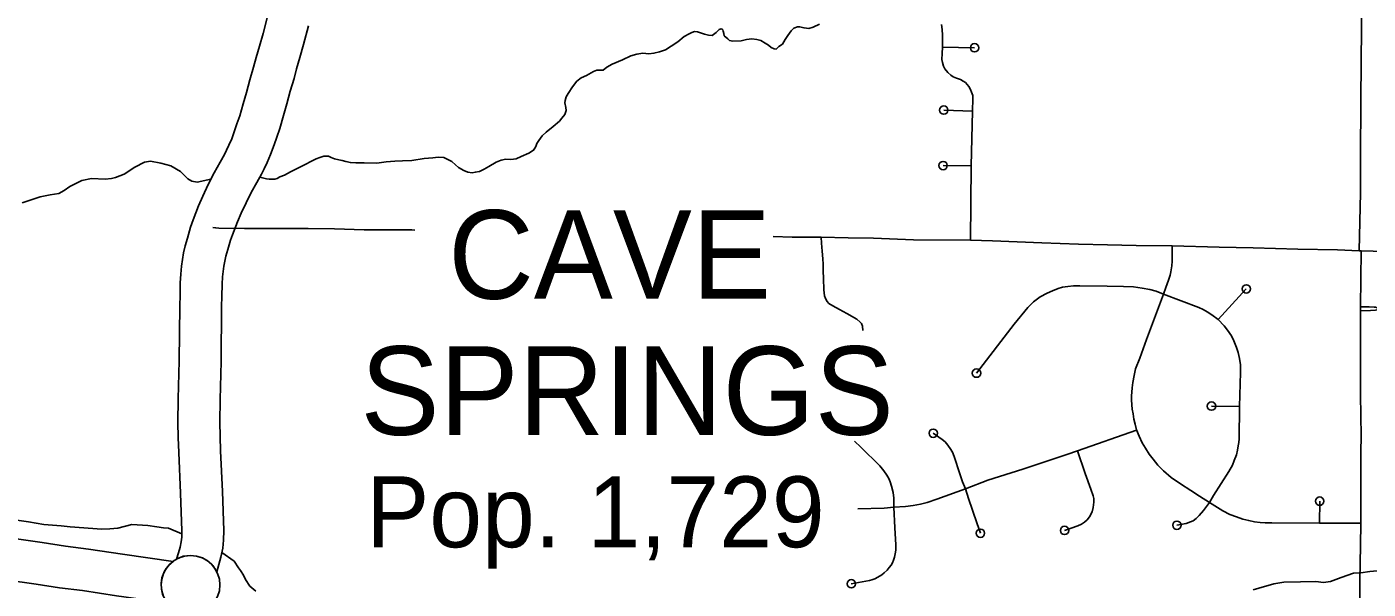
# Model space of a CAD drawing. Extents: x 670147 to 673275, y 705573 to 707613.
# Drawn here: x 671245.2 to 671405.1, y 706403.8 to 706470.8 of the extents above; entities that cross this region are included whole.
import ezdxf

# ---------------------------------------------------------------- set-up
doc = ezdxf.new("R2010")
doc.units = 0
for name, color, linetype in [('10', 7, 'Continuous'), ('24', 7, 'Continuous'), ('33', 7, 'Continuous'), ('34', 7, 'Continuous'), ('35', 7, 'Continuous'), ('6', 7, 'Continuous')]:
    doc.layers.add(name, color=color, linetype=linetype)

msp = doc.modelspace()

# ---------------------------------------------------------------- linework, layer by layer
at = {"layer": '10'}
for points in [[(671273.98, 706472.2), (671273.39, 706470.02), (671272.98, 706468.53), (671272.57, 706467.15), (671272.27, 706466), (671271.83, 706464.52), (671271.41, 706462.99), (671271.02, 706461.63), (671270.61, 706460.21), (671270.29, 706459.25), (671270.01, 706458.41), (671269.67, 706457.48), (671269.33, 706456.72), (671269.05, 706456.13), (671268.79, 706455.6), (671268.28, 706454.69), (671267.56, 706453.42), (671266.87, 706452.03), (671266.21, 706450.64), (671265.72, 706449.48), (671265.07, 706447.8), (671264.75, 706446.95), (671264.38, 706445.62), (671264.13, 706444.74), (671263.93, 706443.9), (671263.8, 706443.09), (671263.67, 706442.31), (671263.58, 706441.34), (671263.53, 706440.33), (671263.51, 706438.83), (671263.46, 706437.59), (671263.4, 706431), (671263.29, 706426.5), (671263.26, 706423.68), (671263.29, 706421.87), (671263.34, 706420.11), (671263.57, 706415.25), (671263.72, 706410.75), (671263.71, 706409.99), (671263.65, 706409.46), (671263.52, 706408.8), (671263.33, 706408.13), (671263.1, 706407.39), (671263.88, 706407.72), (671264.74, 706407.82), (671265.47, 706407.74), (671266.18, 706407.54), (671266.89, 706407.09), (671267.41, 706406.61), (671267.89, 706405.88)], [(671267.89, 706405.88), (671268.38, 706407.63), (671268.59, 706408.69), (671268.7, 706409.66), (671268.72, 706410.79), (671268.57, 706415.45), (671268.33, 706420.29), (671268.29, 706421.98), (671268.26, 706423.7), (671268.29, 706426.41), (671268.4, 706430.92), (671268.46, 706437.48), (671268.5, 706438.7), (671268.53, 706440.17), (671268.57, 706441.01), (671268.63, 706441.68), (671268.73, 706442.28), (671268.83, 706442.91), (671268.97, 706443.48), (671269.19, 706444.28), (671269.51, 706445.4), (671269.74, 706446.02), (671270.35, 706447.59), (671270.78, 706448.6), (671271.37, 706449.86), (671271.97, 706451.07), (671272.64, 706452.25), (671273.2, 706453.25), (671273.53, 706453.91), (671273.89, 706454.64), (671274.3, 706455.61), (671274.73, 706456.76), (671275.04, 706457.69), (671275.38, 706458.72), (671275.83, 706460.25), (671276.22, 706461.65), (671276.64, 706463.14), (671277.09, 706464.65), (671277.39, 706465.81), (671277.79, 706467.16), (671278.22, 706468.71), (671278.81, 706470.94)], [(671237.72, 706410.78), (671236.95, 706405.84), (671238.96, 706405.53), (671242.71, 706404.93), (671246.36, 706404.41), (671249.15, 706403.98), (671251.89, 706403.63), (671255.92, 706403.02), (671262, 706402.16)], [(671262, 706402.16), (671261.67, 706402.7), (671261.43, 706403.2), (671261.3, 706403.8), (671261.26, 706404.49), (671261.35, 706405.17), (671261.66, 706405.94), (671262.15, 706406.65), (671262.67, 706407.12), (671256.64, 706407.97), (671252.58, 706408.59), (671249.85, 706408.94), (671247.09, 706409.36), (671243.46, 706409.87), (671239.74, 706410.47), (671237.72, 706410.78)]]:
    msp.add_lwpolyline(points, dxfattribs=at)
at = {"layer": '24'}
msp.add_circle((671264.76, 706404.31), 3.5, dxfattribs=at)
at = {"layer": '33'}
for points in [[(671404.89, 706523.26), (671404.85, 706517.28), (671404.73, 706508.39), (671404.6, 706499.31), (671404.6, 706498.67), (671404.43, 706487.6), (671404.29, 706479.71), (671404.3, 706479.15), (671404.27, 706473.95), (671404.28, 706473.36), (671404.3, 706470.78)], [(671354.22, 706471.1), (671354.31, 706470.51), (671354.34, 706469.84), (671354.35, 706468.38), (671354.33, 706467.65), (671354.29, 706466.93), (671354.35, 706466.55), (671354.46, 706466.13), (671354.65, 706465.82), (671355.01, 706465.36), (671355.36, 706465.05), (671355.64, 706464.88), (671356.03, 706464.72), (671356.49, 706464.54), (671356.83, 706464.35), (671357.08, 706464.17), (671357.31, 706463.95), (671357.5, 706463.7), (671357.69, 706463.37), (671357.83, 706463.05), (671357.96, 706462.64), (671357.98, 706462.29), (671357.92, 706460.78), (671357.79, 706454.27), (671357.7, 706445.4)], [(671358.18, 706468.33), (671354.35, 706468.38)], [(671354.51, 706460.9), (671357.92, 706460.78)], [(671354.43, 706454.28), (671357.79, 706454.27)], [(671267.4, 706446.91), (671267.75, 706446.85), (671268.11, 706446.81), (671271.17, 706446.79), (671274.81, 706446.79), (671278.78, 706446.77), (671281.92, 706446.73), (671285.45, 706446.64), (671288.36, 706446.64), (671291.14, 706446.61), (671291.48, 706446.6)], [(671334.16, 706445.82), (671336.43, 706445.74), (671339.89, 706445.77), (671343.1, 706445.69), (671346.14, 706445.64), (671350.9, 706445.44), (671357.7, 706445.4), (671360.3, 706445.33), (671366.18, 706445.09), (671370.57, 706444.93), (671374.01, 706444.86), (671377.45, 706444.78), (671381.72, 706444.72), (671387.33, 706444.55), (671391.36, 706444.47), (671396.71, 706444.33), (671401.43, 706444.24), (671404, 706444.12), (671404.26, 706444.11)], [(671381.72, 706444.72), (671381.72, 706443.56), (671381.72, 706442.88), (671381.68, 706442.35), (671381.58, 706441.63), (671381.48, 706441.23), (671381.3, 706440.62), (671380.96, 706439.75), (671380.71, 706438.98)], [(671404.26, 706444.11), (671404.17, 706437.44), (671404.18, 706436.97), (671404.18, 706433.84), (671404.18, 706429.33), (671404.18, 706426.95), (671404.23, 706422.05), (671404.21, 706420.18), (671404.2, 706416.8), (671404.2, 706413.25), (671404.2, 706411.68), (671404.15, 706409.02), (671404.08, 706404.82), (671404.09, 706400.94), (671404.08, 706398.84), (671404.02, 706394.56), (671403.91, 706386.83), (671403.86, 706380.37), (671403.85, 706379.55), (671403.79, 706376.56), (671403.74, 706372.26), (671403.65, 706366.49)], [(671404.26, 706444.11), (671408.5, 706444.02), (671411.96, 706443.93), (671418.53, 706443.82), (671427.9, 706443.72), (671430.84, 706443.66)], [(671358.41, 706429.55), (671362.91, 706435.37), (671364.54, 706437.38), (671365.21, 706438.03), (671366, 706438.63), (671366.84, 706439.1), (671367.47, 706439.37), (671368.14, 706439.63), (671368.66, 706439.78), (671369.28, 706439.88), (671369.96, 706439.95), (671370.71, 706439.95), (671373.98, 706439.92), (671375.94, 706439.87), (671377.11, 706439.83), (671378.14, 706439.69), (671379.08, 706439.53), (671379.8, 706439.33), (671380.71, 706438.98)], [(671380.71, 706438.98), (671378.67, 706433.54), (671377.87, 706431.35), (671377.37, 706430.06), (671377.2, 706429.25), (671377.05, 706428.42), (671376.95, 706427.8), (671376.9, 706427.3), (671376.89, 706426.83), (671376.89, 706426.37), (671376.9, 706425.77), (671376.97, 706425.26), (671377.06, 706424.71), (671377.17, 706424.08), (671377.3, 706423.47), (671377.48, 706422.79), (671377.8, 706422.02), (671378.16, 706421.25), (671378.53, 706420.59), (671379, 706419.88), (671379.44, 706419.29), (671380.03, 706418.59), (671380.69, 706417.89), (671381.62, 706417.11), (671382.7, 706416.37), (671383.94, 706415.55), (671384.97, 706414.87), (671386.18, 706414.13), (671387.76, 706413.14), (671388.61, 706412.72), (671389.4, 706412.41), (671390.16, 706412.15), (671390.84, 706411.98), (671391.53, 706411.83), (671392.21, 706411.75), (671392.8, 706411.7), (671393.59, 706411.7), (671399.26, 706411.67), (671404.2, 706411.68)], [(671386.18, 706414.13), (671386.66, 706414.98), (671388.48, 706417.82), (671388.92, 706418.57), (671389.12, 706419.15), (671389.38, 706419.8), (671389.5, 706420.36), (671389.6, 706420.88), (671389.67, 706421.3), (671389.69, 706421.73), (671389.76, 706425.58), (671389.86, 706429.62), (671389.85, 706430.52), (671389.75, 706431.29), (671389.59, 706432), (671389.4, 706432.62), (671389.08, 706433.4), (671388.78, 706434), (671388.3, 706434.66), (671387.9, 706435.17), (671387.19, 706435.94), (671386.46, 706436.49), (671385.9, 706436.87), (671385.41, 706437.15), (671384.92, 706437.38), (671380.71, 706438.98)], [(671387.19, 706435.94), (671390.56, 706439.59)], [(671404.17, 706437.44), (671405.18, 706437.44), (671405.8, 706437.43), (671405.94, 706437.41), (671406.16, 706437.33), (671406.47, 706437.22), (671406.14, 706437.1), (671405.94, 706437.04), (671405.36, 706437.01), (671404.2, 706436.98)], [(671389.76, 706425.58), (671386.41, 706425.62)], [(671344.25, 706413.36), (671347.42, 706413.47), (671348.57, 706413.56), (671349.96, 706413.67), (671350.85, 706413.79), (671351.73, 706413.94), (671352.53, 706414.15), (671353.69, 706414.55), (671357.09, 706415.75), (671359.77, 706416.78), (671363.93, 706418.09), (671369.18, 706419.87), (671370.44, 706420.29), (671377.48, 706422.74)], [(671348.57, 706413.56), (671348.55, 706414.66), (671348.47, 706415.34), (671348.28, 706416.09), (671348.12, 706416.61), (671347.95, 706416.99), (671347.71, 706417.38), (671347.36, 706417.9), (671346.88, 706418.49), (671344.61, 706420.71), (671343.89, 706421.44)], [(671357.09, 706415.75), (671356.75, 706416.59), (671356.36, 706417.77), (671355.82, 706419.39), (671355.58, 706420.07), (671355.36, 706420.46), (671355, 706420.95), (671354.67, 706421.35), (671354.3, 706421.66), (671353.25, 706422.39)], [(671370.44, 706420.29), (671371.34, 706417.57), (671372.05, 706415.73), (671372.3, 706414.92), (671372.38, 706414.61), (671372.4, 706414.19), (671372.32, 706413.53), (671372.18, 706413.04), (671371.89, 706412.44), (671371.6, 706412.07), (671371.28, 706411.8), (671370.9, 706411.56), (671370.5, 706411.36), (671368.9, 706410.81)], [(671357.09, 706415.75), (671357.44, 706414.61), (671358.44, 706411.73), (671358.88, 706410.47)], [(671348.57, 706413.56), (671348.68, 706411.13), (671348.78, 706409.09), (671348.8, 706408.47), (671348.73, 706408), (671348.63, 706407.61), (671348.52, 706407.25), (671348.4, 706406.96), (671348.23, 706406.68), (671348.02, 706406.39), (671347.75, 706406.07), (671347.41, 706405.75), (671347.11, 706405.5), (671346.67, 706405.22), (671346.28, 706405.04), (671345.93, 706404.92), (671345.65, 706404.84), (671343.49, 706404.45)], [(671386.18, 706414.13), (671385.46, 706413.17), (671384.96, 706412.58), (671384.57, 706412.21), (671384.21, 706411.96), (671383.9, 706411.81), (671383.39, 706411.62), (671382.29, 706411.42)], [(671399.26, 706411.67), (671399.3, 706414.29)]]:
    msp.add_lwpolyline(points, dxfattribs=at)
for centre in [(671358.18, 706468.33), (671354.51, 706460.9), (671354.43, 706454.28), (671390.56, 706439.59), (671358.41, 706429.55), (671386.41, 706425.62), (671353.25, 706422.39), (671399.3, 706414.29), (671368.9, 706410.81), (671382.29, 706411.42), (671358.88, 706410.47), (671343.49, 706404.45)]:
    msp.add_circle(centre, 0.5, dxfattribs=at)
at = {"layer": '34'}
for points in [[(671403.99, 706444.17), (671404.15, 706451.03), (671404.15, 706455.11), (671404.19, 706462.16), (671404.3, 706470.78)], [(671339.89, 706445.77), (671339.93, 706445.05), (671340.01, 706444.09), (671340.09, 706443.19), (671340.12, 706442.54), (671340.15, 706441.73), (671340.18, 706440.81), (671340.23, 706439.47), (671340.3, 706438.78), (671340.4, 706438.46), (671340.61, 706438.08), (671340.83, 706437.85), (671341.3, 706437.57), (671342.09, 706437.15), (671342.96, 706436.64), (671344.14, 706435.98), (671344.55, 706435.62), (671344.7, 706435.47), (671344.83, 706435.14), (671344.86, 706434.63)]]:
    msp.add_lwpolyline(points, dxfattribs=at)
at = {"layer": '35'}
for points in [[(671304.16, 706455.37), (671305.06, 706455.78), (671305.64, 706456.11), (671305.78, 706456.35), (671305.88, 706456.56), (671306, 706456.93), (671306.24, 706457.29), (671306.66, 706457.82), (671307.15, 706458.27), (671307.98, 706458.96), (671308.72, 706459.58), (671309.01, 706459.92), (671309.36, 706460.39), (671309.52, 706460.83), (671309.49, 706461.21), (671309.34, 706461.75), (671309.38, 706462.06), (671309.52, 706462.46), (671309.76, 706462.88), (671310.28, 706463.66), (671310.77, 706464.33), (671311.3, 706464.73), (671311.95, 706465.02), (671312.77, 706465.49), (671313.15, 706465.67), (671313.55, 706465.67), (671313.93, 706465.67), (671314.37, 706466), (671315.01, 706466.37), (671316.21, 706466.9), (671317.22, 706467.37), (671317.95, 706467.57), (671318.66, 706467.68), (671319.37, 706467.61), (671319.96, 706467.68), (671320.64, 706467.86), (671321.34, 706468.08), (671322.03, 706468.51), (671322.81, 706469.04), (671323.58, 706469.66), (671324.17, 706470), (671324.5, 706470.15), (671324.81, 706470.26), (671325.17, 706470.22), (671325.53, 706470.09), (671325.99, 706469.93), (671326.48, 706469.82), (671326.91, 706469.8), (671327.37, 706470.16), (671327.74, 706470.49), (671327.98, 706470.6), (671328.1, 706470.55), (671328.17, 706470.46), (671328.21, 706470.31), (671328.3, 706470.04), (671328.36, 706469.75), (671328.79, 706469.37), (671328.99, 706469.2), (671329.37, 706469.13), (671330.35, 706469.15), (671330.99, 706469.31), (671331.64, 706469.38), (671332.22, 706469.31), (671332.69, 706469.18), (671333.24, 706468.88), (671333.64, 706468.64), (671333.96, 706468.37), (671334.29, 706468.19), (671334.53, 706468.17), (671334.87, 706468.48), (671335.31, 706468.77), (671335.61, 706469.31), (671335.94, 706469.8)], [(671335.94, 706469.8), (671336.31, 706470.36), (671336.64, 706470.67), (671337.06, 706470.83), (671337.33, 706470.82), (671337.87, 706470.69), (671338.44, 706470.63), (671338.94, 706470.78), (671339.72, 706471.12)], [(671244.71, 706449.84), (671246.84, 706450.56), (671248.02, 706450.79), (671249.06, 706450.97), (671249.69, 706451.33), (671250.37, 706451.78), (671251.82, 706452.51), (671252.95, 706452.74), (671254.6, 706452.67), (671255.35, 706452.75), (671255.82, 706452.85), (671256.85, 706453.28), (671258.12, 706454.1), (671259.25, 706454.68), (671260, 706454.81), (671261.2, 706454.59), (671262.39, 706454.25), (671263.56, 706453.57), (671264.44, 706452.69), (671264.89, 706452.44), (671265.55, 706452.31), (671267.18, 706452.67)], [(671273, 706452.9), (671273.82, 706452.7), (671274.13, 706452.66), (671274.4, 706452.66), (671274.78, 706452.65), (671275.07, 706452.75), (671275.4, 706452.95), (671275.94, 706453.15), (671276.67, 706453.53), (671277.85, 706454.13), (671279.72, 706455.1), (671280.15, 706455.24), (671280.64, 706455.4), (671280.91, 706455.4), (671281.2, 706455.39), (671281.53, 706455.26), (671281.91, 706455.1), (671282.44, 706454.95), (671282.82, 706454.9), (671283.27, 706454.79), (671283.8, 706454.64), (671284.47, 706454.61), (671285.46, 706454.61), (671286.95, 706454.59), (671288.06, 706454.73), (671289.09, 706454.81), (671290, 706454.86), (671291.14, 706454.91), (671292.59, 706455.11), (671293.64, 706455.2), (671294.28, 706455.28), (671294.93, 706455.24), (671295.43, 706454.99), (671295.9, 706454.77), (671296.34, 706454.39), (671296.68, 706454.06), (671297.3, 706453.68), (671297.81, 706453.5), (671298.3, 706453.44), (671298.68, 706453.5), (671299.19, 706453.59), (671299.73, 706453.84), (671300.31, 706454.19), (671301.16, 706454.7), (671301.76, 706454.93), (671302.33, 706455.04), (671302.92, 706455.01), (671303.54, 706455.1), (671304.16, 706455.37)], [(671250.4, 706411.25), (671249.35, 706411.34), (671247.27, 706411.52), (671245.44, 706411.84), (671239.78, 706412.63), (671235.07, 706413.32), (671233.23, 706413.74), (671230.06, 706414.11)], [(671263.71, 706410.39), (671262.11, 706411.07), (671261.55, 706411.13), (671260.72, 706411.23), (671259.66, 706411.38), (671257.77, 706411.5), (671256.1, 706411.09), (671255.15, 706411), (671254.18, 706410.94), (671250.4, 706411.25)], [(671426.81, 706410.11), (671422.88, 706409.25), (671419.78, 706408.58), (671416.9, 706408.06), (671414.08, 706407.53), (671410.03, 706406.67), (671407.54, 706406.12), (671405.27, 706405.9), (671404.19, 706405.76), (671403.33, 706405.7), (671401.85, 706405.2), (671400.6, 706404.73), (671399.75, 706404.59), (671398.83, 706404.7), (671397, 706404.68), (671395.04, 706404.62), (671393.82, 706404.45), (671392.07, 706403.94), (671391.38, 706403.73)], [(671272.53, 706403.55), (671271.82, 706404.17), (671271.3, 706404.96), (671271.06, 706405.48), (671270.69, 706406.04), (671270.47, 706406.34), (671269.94, 706407.13), (671268.49, 706408.18)]]:
    msp.add_lwpolyline(points, dxfattribs=at)

# ---------------------------------------------------------------- texts
at = {"layer": '6'}
for s, height, p in [('CAVE', 10.56, (671295.46, 706438.41)), ('SPRINGS', 10.56, (671285, 706422.19)), ('Pop. 1,729', 8.448, (671285.67, 706408.8))]:
    msp.add_text(s, height=height, dxfattribs=at).set_placement(p)

doc.saveas('drawing.dxf')
